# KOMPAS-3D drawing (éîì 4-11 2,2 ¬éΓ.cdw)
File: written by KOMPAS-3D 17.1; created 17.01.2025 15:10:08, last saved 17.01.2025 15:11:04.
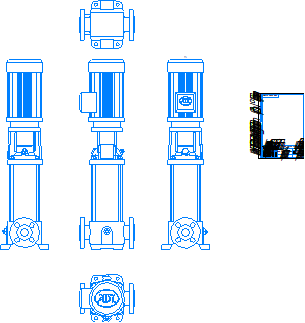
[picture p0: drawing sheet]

Sheet 1: A4, portrait

Title block, sheet 1: name: ВМН 4-11 2,2 кВт; designation: ВМН 4-11 2,2 кВт; sheets: 1; sheet format: A4; stored path: \\adlc.lan\data\АДЛ_ПКД\3D-модели\ADL production\Насосы ГРАНПАМП\Насосы ВМН\ВМН4\KOMPAS 2D\ВМН 4-11 2,2 кВт.cdw

Views: Вид 1, Спереди, Проекционный вид 2, Проекционный вид 3, Проекционный вид 4, Проекционный вид 5
Referenced files in \\adlc.lan\data\АДЛ_ПКД\3D-модели\ADL production\Насосы ГРАНПАМП\Насосы ВМН\ВМН4\KOMPAS 3D\: ВМН 4-11 2,2 кВт.m3d
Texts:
  Andrey
  АДЛ
Dimensions and other numbers on the sheet: 1:1; 1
